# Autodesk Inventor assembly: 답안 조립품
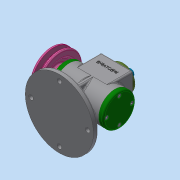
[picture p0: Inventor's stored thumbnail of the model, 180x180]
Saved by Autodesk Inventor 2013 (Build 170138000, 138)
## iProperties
Created: 2020-09
Part Number: 답안 조립품
Document SubType Name: Assembly
Designer: dgall
Author: dgall
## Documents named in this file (18)
- C:\Users\dgall\Desktop\600906V1018\답안 조립품.iam
- C:\Users\dgall\Desktop\600906V1018\본체.ipt
- C:\Users\dgall\Desktop\600906V1018\베어링 6203.ipt
- C:\Users\dgall\Desktop\600906V1018\편심축.ipt
- C:\Users\dgall\Desktop\600906V1018\앞커버.ipt
- C:\Users\dgall\Desktop\600906V1018\뒤커버.ipt
- C:\Users\dgall\Desktop\600906V1018\상부커버.ipt
- C:\Users\dgall\Desktop\600906V1018\오일 실 17 30 5.ipt
- C:\Users\dgall\Desktop\600906V1018\키 4x4x12.ipt
- C:\Users\dgall\Desktop\600906V1018\V-벨트풀리.ipt
- C:\Users\dgall\Desktop\600906V1018\평와셔.ipt
- C:\Users\dgall\Desktop\600906V1018\스프링와셔.ipt
- C:\Users\dgall\Desktop\600906V1018\볼트 M4.ipt
- C:\Users\dgall\Desktop\600906V1018\가이드부시.ipt
- C:\Users\dgall\Desktop\600906V1018\멈춤링.ipt
- C:\Users\dgall\Desktop\600906V1018\슬라이더.ipt
- C:\Users\dgall\Desktop\600906V1018\스프링조립용 와셔.ipt
- C:\Users\dgall\Desktop\600906V1018\가변스프링.ipt
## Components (3 placed, 3 different names)
1. V-벨트풀리:1
2. 가이드부시:1
3. 가변스프링:1
